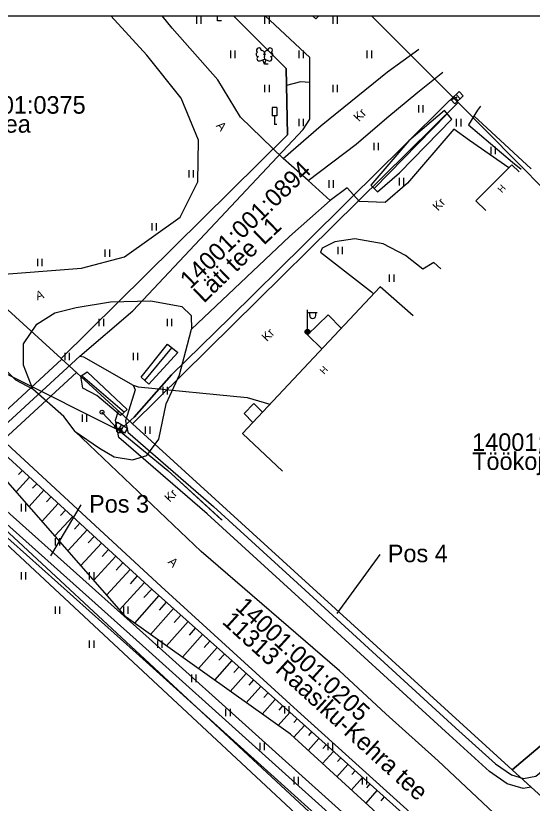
# Model space of a CAD drawing. Extents: x 567864 to 568657, y 6579839 to 6580994.
# Drawn here: x 568425.2 to 568478.2, y 6580410.7 to 6580491.5 of the extents above; entities that cross this region are included whole.
import ezdxf

# ---------------------------------------------------------------- set-up
doc = ezdxf.new("R2010")
doc.units = 0
for name, color, linetype in [('AED', 7, 'Continuous'), ('ELRAJATISMP', 7, 'Continuous'), ('HALJASTUS', 7, 'Continuous'), ('HOONE', 7, 'Continuous'), ('KASUTUSALA', 7, 'Continuous'), ('KPOHULIIN', 7, 'Continuous'), ('LIIKLUS', 7, 'Continuous'), ('MPKAABEL', 7, 'Continuous'), ('MPOHULIIN', 7, 'Continuous'), ('PIIR', 7, 'Continuous'), ('POST', 7, 'Continuous'), ('PR_SIDE', 7, 'Continuous'), ('PUU', 7, 'Continuous'), ('RELJEEF', 7, 'Continuous'), ('TEE', 7, 'Continuous'), ('VORMISTUS_3', 7, 'Continuous')]:
    doc.layers.add(name, color=color, linetype=linetype)

msp = doc.modelspace()

# ---------------------------------------------------------------- linework, layer by layer
at = {"layer": 'AED'}
msp.add_line((568436.38, 6580450.775), (568432.091, 6580454.464), dxfattribs=at)
at = {"layer": 'ELRAJATISMP'}
for p, q in [((568470.216, 6580483.175), (568470.629, 6580482.743)), ((568470.412, 6580483.362), (568470.825, 6580482.931)), ((568436.071, 6580449.542), (568435.765, 6580449.029)), ((568436.304, 6580449.402), (568435.998, 6580448.89))]:
    msp.add_line(p, q, dxfattribs=at)
for points in [[(568469.882, 6580482.855), (568470.746, 6580483.681), (568471.158, 6580483.25), (568470.295, 6580482.424)], [(568435.675, 6580449.778), (568436.7, 6580449.165), (568436.394, 6580448.653), (568435.369, 6580449.266)]]:
    msp.add_lwpolyline(points, close=True, dxfattribs=at)
at = {"layer": 'HALJASTUS'}
for p, q in [((568443.772, 6580491.381), (568443.772, 6580490.619)), ((568444.228, 6580491.381), (568444.228, 6580490.619)), ((568450.772, 6580491.381), (568450.772, 6580490.619)), ((568451.228, 6580491.381), (568451.228, 6580490.619)), ((568457.772, 6580491.381), (568457.772, 6580490.619)), ((568458.228, 6580491.381), (568458.228, 6580490.619)), ((568447.272, 6580487.881), (568447.272, 6580487.119)), ((568447.728, 6580487.881), (568447.728, 6580487.119)), ((568454.272, 6580487.881), (568454.272, 6580487.119)), ((568454.728, 6580487.881), (568454.728, 6580487.119)), ((568461.272, 6580487.881), (568461.272, 6580487.119)), ((568461.728, 6580487.881), (568461.728, 6580487.119)), ((568450.772, 6580484.381), (568450.772, 6580483.619)), ((568451.228, 6580484.381), (568451.228, 6580483.619)), ((568457.772, 6580484.381), (568457.772, 6580483.619)), ((568458.228, 6580484.381), (568458.228, 6580483.619)), ((568466.562, 6580482.291), (568466.562, 6580481.53)), ((568467.017, 6580482.291), (568467.017, 6580481.53)), ((568454.272, 6580480.881), (568454.272, 6580480.119)), ((568454.728, 6580480.881), (568454.728, 6580480.119)), ((568462.026, 6580473.738), (568469.517, 6580481.401)), ((568470.443, 6580480.873), (568470.443, 6580480.112)), ((568470.898, 6580480.873), (568470.898, 6580480.112)), ((568472.25, 6580481.183), (568478.108, 6580475.742)), ((568461.963, 6580478.438), (568461.963, 6580477.677)), ((568462.418, 6580478.438), (568462.418, 6580477.677)), ((568473.978, 6580478.017), (568473.978, 6580477.256)), ((568474.433, 6580478.017), (568474.433, 6580477.256)), ((568442.977, 6580475.614), (568442.977, 6580474.853)), ((568443.432, 6580475.614), (568443.432, 6580474.853)), ((568457.364, 6580474.585), (568457.364, 6580473.823)), ((568457.819, 6580474.585), (568457.819, 6580473.823)), ((568464.577, 6580474.82), (568464.577, 6580474.059)), ((568465.032, 6580474.82), (568465.032, 6580474.059)), ((568439.18, 6580470.19), (568439.18, 6580469.429)), ((568439.635, 6580470.19), (568439.635, 6580469.429)), ((568434.388, 6580467.491), (568434.388, 6580466.73)), ((568434.844, 6580467.491), (568434.844, 6580466.73)), ((568458.269, 6580467.752), (568458.269, 6580466.991)), ((568458.724, 6580467.752), (568458.724, 6580466.991)), ((568427.45, 6580466.521), (568427.45, 6580465.76)), ((568427.905, 6580466.521), (568427.905, 6580465.76)), ((568463.561, 6580464.925), (568463.561, 6580464.164)), ((568464.016, 6580464.925), (568464.016, 6580464.164)), ((568433.772, 6580460.381), (568433.772, 6580459.619)), ((568434.228, 6580460.381), (568434.228, 6580459.619)), ((568440.772, 6580460.381), (568440.772, 6580459.619)), ((568441.228, 6580460.381), (568441.228, 6580459.619)), ((568438.494, 6580454.05), (568441.242, 6580457.406)), ((568430.272, 6580456.881), (568430.272, 6580456.119)), ((568430.728, 6580456.881), (568430.728, 6580456.119)), ((568437.272, 6580456.881), (568437.272, 6580456.119)), ((568437.728, 6580456.881), (568437.728, 6580456.119)), ((568440.324, 6580453.381), (568440.324, 6580452.619)), ((568440.779, 6580453.381), (568440.779, 6580452.619)), ((568432.038, 6580450.564), (568432.038, 6580449.803)), ((568432.493, 6580450.564), (568432.493, 6580449.803)), ((568438.526, 6580449.327), (568438.526, 6580448.566)), ((568438.981, 6580449.327), (568438.981, 6580448.566)), ((568425.772, 6580441.381), (568425.772, 6580440.619)), ((568426.228, 6580441.381), (568426.228, 6580440.619)), ((568429.272, 6580437.881), (568429.272, 6580437.119)), ((568429.728, 6580437.881), (568429.728, 6580437.119)), ((568425.772, 6580434.381), (568425.772, 6580433.619)), ((568426.228, 6580434.381), (568426.228, 6580433.619)), ((568432.772, 6580434.381), (568432.772, 6580433.619)), ((568433.228, 6580434.381), (568433.228, 6580433.619)), ((568429.272, 6580430.881), (568429.272, 6580430.119)), ((568429.728, 6580430.881), (568429.728, 6580430.119)), ((568436.272, 6580430.881), (568436.272, 6580430.119)), ((568436.728, 6580430.881), (568436.728, 6580430.119)), ((568432.772, 6580427.381), (568432.772, 6580426.619)), ((568433.228, 6580427.381), (568433.228, 6580426.619)), ((568439.772, 6580427.381), (568439.772, 6580426.619)), ((568440.228, 6580427.381), (568440.228, 6580426.619)), ((568443.272, 6580423.881), (568443.272, 6580423.119)), ((568443.728, 6580423.881), (568443.728, 6580423.119)), ((568446.772, 6580420.381), (568446.772, 6580419.619)), ((568447.228, 6580420.381), (568447.228, 6580419.619)), ((568452.799, 6580420.654), (568452.799, 6580419.893)), ((568453.254, 6580420.654), (568453.254, 6580419.893)), ((568450.272, 6580416.881), (568450.272, 6580416.119)), ((568450.728, 6580416.881), (568450.728, 6580416.119)), ((568457.272, 6580416.881), (568457.272, 6580416.119)), ((568457.728, 6580416.881), (568457.728, 6580416.119)), ((568453.772, 6580413.381), (568453.772, 6580412.619)), ((568454.228, 6580413.381), (568454.228, 6580412.619)), ((568460.772, 6580413.381), (568460.772, 6580412.619)), ((568461.228, 6580413.381), (568461.228, 6580412.619))]:
    msp.add_line(p, q, dxfattribs=at)
for points in [[(568455.679, 6580491.456), (568456.023, 6580491.13), (568456.344, 6580491.456)], [(568469.23, 6580481.751), (568465.569, 6580478.638), (568461.681, 6580474.088), (568462.36, 6580473.4), (568464.605, 6580475.334), (568469.983, 6580480.833), (568469.23, 6580481.751)], [(568472.919, 6580482.179), (568472.604, 6580481.765), (568471.701, 6580480.282), (568476.216, 6580476.426), (568477.089, 6580475.728)], [(568440.791, 6580457.756), (568441.872, 6580456.916), (568438.89, 6580453.686), (568438.113, 6580454.4), (568440.791, 6580457.756)], [(568436.657, 6580451.066), (568435.99, 6580450.468), (568433.555, 6580452.514), (568432.1, 6580453.247), (568431.917, 6580454.485), (568432.571, 6580454.92), (568436.657, 6580451.066)]]:
    msp.add_lwpolyline(points, dxfattribs=at)
at = {"layer": 'HOONE'}
for points in [[(568476.908, 6580475.43), (568476.153, 6580476.182), (568472.461, 6580472.475), (568473.456, 6580471.485)], [(568466.002, 6580460.689), (568462.617, 6580463.652), (568448.5, 6580448.608), (568452.605, 6580444.756)]]:
    msp.add_lwpolyline(points, dxfattribs=at)
at = {"layer": 'KASUTUSALA'}
msp.add_lwpolyline([(568493.207, 6580374.737), (568460.062, 6580405.872), (568437.58, 6580426.106), (568418.255, 6580443.353), (568417.794, 6580443.764), (568417.1, 6580444.45), (568402.76, 6580458.616), (568388.236, 6580470.827), (568387.31, 6580471.69), (568385.679, 6580473.21), (568386.212, 6580473.528), (568388.359, 6580473.336), (568404.109, 6580460.095), (568418.602, 6580445.777), (568429.97, 6580456.218), (568431.455, 6580454.865), (568420.072, 6580444.412), (568438.915, 6580427.595), (568461.416, 6580407.344), (568494.568, 6580376.202)], dxfattribs=at)
msp.add_lwpolyline([(568477.303, 6580412.2), (568475.657, 6580412.671), (568473.841, 6580413.939), (568469.701, 6580417.689), (568454.272, 6580431.785), (568444.875, 6580440.358), (568435.811, 6580448.207), (568435.47, 6580449.982), (568435.77, 6580450.932), (568437.22, 6580449.61), (568476.19, 6580414.1), (568478.11, 6580412.351)], close=True, dxfattribs=at)
at = {"layer": 'KPOHULIIN'}
msp.add_lwpolyline([(568508.43, 6580360.63), (568460.118, 6580405.359), (568402.883, 6580458.504), (568384.68, 6580466.246)], dxfattribs=at)
at = {"layer": 'LIIKLUS'}
for p, q in [((568451.53, 6580482.056), (568451.53, 6580481.206)), ((568452.03, 6580482.056), (568451.53, 6580482.056)), ((568452.03, 6580482.056), (568452.03, 6580481.206)), ((568452.03, 6580481.206), (568451.53, 6580481.206)), ((568451.78, 6580481.206), (568451.78, 6580480.306)), ((568452.03, 6580480.306), (568451.78, 6580480.306))]:
    msp.add_line(p, q, dxfattribs=at)
at = {"layer": 'MPKAABEL'}
for points in [[(568435.851, 6580448.911), (568437.38, 6580450.298), (568441.22, 6580454.614), (568447.245, 6580460.504), (568454.8, 6580467.949), (568459.571, 6580472.72), (568464.936, 6580477.992), (568469.741, 6580482.773), (568470.51, 6580483.116)], [(568470.51, 6580483.116), (568469.741, 6580482.773), (568464.936, 6580477.992), (568459.571, 6580472.72), (568454.8, 6580467.949), (568447.245, 6580460.504), (568441.22, 6580454.614), (568437.38, 6580450.298), (568435.851, 6580448.911)], [(568435.851, 6580448.911), (568440.843, 6580444.81), (568446.413, 6580439.712)], [(568435.851, 6580448.911), (568440.841, 6580444.812), (568446.315, 6580439.802)]]:
    msp.add_lwpolyline(points, dxfattribs=at)
at = {"layer": 'MPOHULIIN'}
msp.add_lwpolyline([(568435.851, 6580448.911), (568391.527, 6580471.097), (568384.68, 6580475.615)], dxfattribs=at)
at = {"layer": 'PIIR'}
for points in [[(568391.299, 6580491.456), (568392.03, 6580490.79), (568429.88, 6580456.3), (568437.22, 6580449.61), (568476.19, 6580414.1), (568508.43, 6580384.732)], [(568447.578, 6580491.456), (568452.98, 6580486.06), (568453.13, 6580479.23), (568429.88, 6580456.3), (568392.03, 6580490.79), (568392.661, 6580491.456)], [(568461.731, 6580491.456), (568470.64, 6580482.56), (568437.22, 6580449.61), (568429.88, 6580456.3), (568453.13, 6580479.23), (568452.98, 6580486.06), (568447.578, 6580491.456)], [(568508.43, 6580485.337), (568485.66, 6580467.38), (568470.64, 6580482.56), (568461.731, 6580491.456)], [(568508.43, 6580441.348), (568476.19, 6580414.1), (568437.22, 6580449.61), (568470.64, 6580482.56), (568485.66, 6580467.38), (568508.43, 6580485.337)], [(568508.43, 6580358.861), (568387.31, 6580471.69), (568384.68, 6580474.141)], [(568384.68, 6580470.154), (568387.31, 6580471.69), (568508.43, 6580358.861)], [(568508.43, 6580384.732), (568476.19, 6580414.1), (568508.43, 6580441.348)]]:
    msp.add_lwpolyline(points, dxfattribs=at)
at = {"layer": 'POST'}
for p, q in [((568455.176, 6580459.279), (568455.176, 6580461.279)), ((568455.176, 6580461.029), (568456.176, 6580461.029)), ((568455.402, 6580460.708), (568455.402, 6580461.029)), ((568456.015, 6580460.708), (568456.015, 6580461.029)), ((568455.176, 6580459.029), (568455.176, 6580459.029))]:
    msp.add_line(p, q, dxfattribs=at)
msp.add_lwpolyline([(568434.08, 6580450.796), (568435.851, 6580448.911)], dxfattribs=at)
for centre, radius in [((568455.176, 6580459.029), 0.25), ((568455.176, 6580459.029), 0.225), ((568455.176, 6580459.029), 0.2), ((568455.176, 6580459.029), 0.175), ((568455.176, 6580459.029), 0.15), ((568455.176, 6580459.029), 0.125), ((568455.176, 6580459.029), 0.1), ((568455.176, 6580459.029), 0.075), ((568455.176, 6580459.029), 0.05), ((568455.176, 6580459.029), 0.025), ((568434.08, 6580450.796), 0.2), ((568435.851, 6580448.911), 0.25)]:
    msp.add_circle(centre, radius, dxfattribs=at)
msp.add_arc((568455.709, 6580460.708), 0.306, 180, 0, dxfattribs=at)
at = {"layer": 'PR_SIDE'}
for points in [[(568455.401, 6580484.611), (568455.401, 6580487.168), (568450.837, 6580491.456)], [(568365.055, 6580475.025), (568365.72, 6580474.689), (568366.357, 6580474.88), (568372.77, 6580480.661), (568373.5, 6580480.629), (568382.621, 6580470.383), (568382.924, 6580470.401), (568386.446, 6580472.503), (568387.957, 6580472.369), (568403.435, 6580459.356), (568418.48, 6580444.494), (568418.81, 6580444.61), (568431.813, 6580456.552), (568437.233, 6580461.195), (568454.71, 6580479.772), (568455.401, 6580480.844), (568455.401, 6580484.611)], [(568455.401, 6580484.611), (568454.444, 6580484.677), (568453.019, 6580484.299)], [(568431.813, 6580456.552), (568432.198, 6580456.461), (568437.292, 6580453.582)], [(568437.292, 6580453.582), (568437.498, 6580453.084), (568436.5, 6580449.922), (568436.728, 6580448.737), (568445.54, 6580441.106), (568454.946, 6580432.524), (568470.375, 6580418.429), (568474.466, 6580414.723), (568476.093, 6580413.587), (568477.351, 6580413.227), (568478.62, 6580413.465), (568488.626, 6580421.658), (568489.887, 6580422.056), (568492.08, 6580421.21), (568508.662, 6580420.568), (568511.852, 6580420.197), (568512.12, 6580420.126), (568512.341, 6580419.855)], [(568437.292, 6580453.582), (568437.782, 6580453.404), (568448.982, 6580452.292), (568451.31, 6580451.603)], [(568418.48, 6580444.494), (568438.248, 6580426.851), (568460.739, 6580406.609), (568493.888, 6580375.47), (568520.606, 6580350.928), (568532.176, 6580339.842), (568577.376, 6580298.14), (568583.801, 6580292.735), (568596.758, 6580277.054), (568604.332, 6580268.007), (568619.547, 6580250.982), (568628.574, 6580238.417), (568627.426, 6580222.172)]]:
    msp.add_lwpolyline(points, dxfattribs=at)
at = {"layer": 'PUU'}
for p, q in [((568445.95, 6580490.942), (568445.95, 6580491.442)), ((568446.35, 6580490.942), (568445.95, 6580490.942)), ((568450.307, 6580486.829), (568450.752, 6580487.004)), ((568450.747, 6580486.494), (568450.572, 6580486.934)), ((568450.747, 6580486.494), (568450.927, 6580486.934)), ((568451.127, 6580486.494), (568450.747, 6580486.494)), ((568450.752, 6580487.004), (568451.192, 6580486.824))]:
    msp.add_line(p, q, dxfattribs=at)
msp.add_lwpolyline([(568450.752, 6580487.499), (568450.732, 6580487.424), (568450.732, 6580487.404), (568450.742, 6580487.374), (568450.762, 6580487.339), (568450.767, 6580487.319), (568450.752, 6580487.284), (568450.727, 6580487.234), (568450.722, 6580487.209), (568450.727, 6580487.194), (568450.737, 6580487.164), (568450.772, 6580487.104), (568450.777, 6580487.084), (568450.772, 6580487.064), (568450.757, 6580487.029), (568450.752, 6580487.004)], dxfattribs=at)
for centre, radius, start, end in [((568445.95, 6580491.942), 0.5, 256.7038, 283.2962), ((568450.19, 6580487.908), 0.256, 111.50269, 232.51731), ((568450.19, 6580487.908), 0.256, 350.48556, 111.50017), ((568451.326, 6580487.899), 0.256, 67.6168, 188.63142), ((568451.326, 6580487.899), 0.256, 306.59966, 67.61428), ((568450.116, 6580487.496), 0.224, 111.43041, 274.49868), ((568450.221, 6580487.052), 0.237, 111.50143, 291.50036), ((568450.525, 6580487.657), 0.224, 308.50412, 111.57247), ((568450.751, 6580487.261), 0.237, 66.76552, 111.50149), ((568450.988, 6580487.653), 0.225, 67.7016, 230.51262), ((568451.282, 6580487.044), 0.237, 247.61661, 67.61554), ((568451.394, 6580487.486), 0.224, 264.6183, 67.68657)]:
    msp.add_arc(centre, radius, start, end, dxfattribs=at)
at = {"layer": 'RELJEEF'}
for p, q in [((568425.915, 6580444.811), (568425.526, 6580444.387)), ((568426.652, 6580444.135), (568425.28, 6580442.639)), ((568428.126, 6580442.784), (568426.605, 6580441.126)), ((568427.389, 6580443.459), (568426.955, 6580442.986)), ((568428.863, 6580442.108), (568428.385, 6580441.586)), ((568429.6, 6580441.432), (568427.931, 6580439.612)), ((568430.337, 6580440.756), (568429.814, 6580440.185)), ((568431.074, 6580440.08), (568429.256, 6580438.098)), ((568432.548, 6580438.728), (568430.582, 6580436.584)), ((568431.811, 6580439.404), (568431.243, 6580438.785)), ((568433.285, 6580438.052), (568432.673, 6580437.384)), ((568434.022, 6580437.376), (568431.907, 6580435.07)), ((568434.759, 6580436.7), (568434.102, 6580435.984)), ((568435.496, 6580436.024), (568433.232, 6580433.556)), ((568436.97, 6580434.672), (568434.558, 6580432.043)), ((568436.233, 6580435.348), (568435.531, 6580434.584)), ((568437.706, 6580433.996), (568436.961, 6580433.183)), ((568438.443, 6580433.32), (568435.883, 6580430.529)), ((568439.18, 6580432.644), (568438.39, 6580431.783)), ((568439.926, 6580431.978), (568437.41, 6580429.155)), ((568441.419, 6580430.647), (568439.05, 6580427.99)), ((568440.672, 6580431.312), (568439.94, 6580430.49)), ((568442.165, 6580429.981), (568441.477, 6580429.209)), ((568442.912, 6580429.316), (568440.69, 6580426.824)), ((568443.658, 6580428.651), (568443.014, 6580427.928)), ((568444.405, 6580427.985), (568442.33, 6580425.658)), ((568445.897, 6580426.654), (568443.97, 6580424.492)), ((568445.151, 6580427.32), (568444.551, 6580426.646)), ((568446.644, 6580425.989), (568446.088, 6580425.365)), ((568447.39, 6580425.323), (568445.61, 6580423.326)), ((568448.137, 6580424.658), (568447.625, 6580424.083)), ((568448.883, 6580423.993), (568447.25, 6580422.16)), ((568450.376, 6580422.662), (568448.89, 6580420.994)), ((568449.63, 6580423.327), (568449.162, 6580422.802)), ((568451.123, 6580421.996), (568450.699, 6580421.521)), ((568451.869, 6580421.331), (568450.53, 6580419.828)), ((568452.616, 6580420.665), (568452.236, 6580420.239)), ((568453.362, 6580420), (568452.17, 6580418.662)), ((568454.108, 6580419.334), (568453.772, 6580418.958)), ((568454.853, 6580418.667), (568453.767, 6580417.454)), ((568455.598, 6580418), (568455.27, 6580417.634)), ((568456.343, 6580417.333), (568455.244, 6580416.106)), ((568457.088, 6580416.665), (568456.756, 6580416.295)), ((568457.833, 6580415.998), (568456.721, 6580414.757)), ((568458.578, 6580415.331), (568458.242, 6580414.957)), ((568459.322, 6580414.664), (568458.198, 6580413.408)), ((568460.067, 6580413.997), (568459.728, 6580413.618)), ((568460.812, 6580413.33), (568459.675, 6580412.06)), ((568461.557, 6580412.662), (568461.214, 6580412.279)), ((568462.302, 6580411.995), (568461.152, 6580410.711)), ((568463.047, 6580411.328), (568462.7, 6580410.941))]:
    msp.add_line(p, q, dxfattribs=at)
for points in [[(568508.43, 6580369.908), (568508.363, 6580369.97), (568491.192, 6580385.824), (568473.185, 6580402.248), (568453.996, 6580419.435), (568439.254, 6580432.576), (568424.484, 6580446.124), (568410.28, 6580459.769), (568392.732, 6580475.544), (568387.587, 6580476.456), (568384.68, 6580475.798)], [(568508.43, 6580367.153), (568506.784, 6580368.671), (568490.34, 6580384.468), (568471.539, 6580401.225), (568453.41, 6580417.781), (568436.551, 6580429.766), (568424.43, 6580443.611), (568407.632, 6580458.36), (568391.91, 6580472.015), (568385.007, 6580473.1), (568384.68, 6580472.903)]]:
    msp.add_lwpolyline(points, dxfattribs=at)
at = {"layer": 'TEE'}
for points in [[(568508.43, 6580378.848), (568495.331, 6580390.846), (568482.748, 6580402.025), (568475.413, 6580408.617), (568468.573, 6580415.051), (568463.218, 6580419.847), (568458.453, 6580424.255), (568444.275, 6580436.505), (568431.318, 6580448.81), (568430.178, 6580450.348), (568426.969, 6580453.169), (568425.251, 6580454.077), (568411.891, 6580467.485), (568409.943, 6580469.266), (568402.862, 6580475.838), (568393.707, 6580484.18), (568385.876, 6580491.456)], [(568411.891, 6580467.485), (568415.882, 6580465.074), (568420.903, 6580464.715), (568425.819, 6580465.089), (568431.98, 6580465.58), (568436.401, 6580466.715), (568442.096, 6580470.806), (568443.907, 6580474.414), (568443.977, 6580478.683), (568442.212, 6580482.999), (568438.678, 6580487.427), (568434.981, 6580491.456)], [(568426.969, 6580453.169), (568426.04, 6580455.624), (568426.04, 6580457.796), (568427.401, 6580459.807), (568429.249, 6580460.974), (568431.436, 6580461.533), (568434.953, 6580462.101), (568439.093, 6580462.214), (568442.269, 6580461.647), (568443.217, 6580460.715), (568443.282, 6580459.32), (568453.309, 6580468.816), (568457.506, 6580472.505), (568455.25, 6580474.572), (568452.658, 6580476.809), (568448.298, 6580481.07), (568445.963, 6580484.873), (568441.272, 6580490.194), (568440.254, 6580491.456)], [(568452.658, 6580476.809), (568456.583, 6580480.188), (568463.384, 6580485.693), (568466.608, 6580488.043)], [(568455.25, 6580474.572), (568460.16, 6580478.279), (568463.297, 6580480.985), (568466.509, 6580483.605), (568469.046, 6580485.675)], [(568475.819, 6580475.846), (568471.809, 6580478.673), (568470.185, 6580479.817), (568465.421, 6580474.296), (568463.153, 6580472.286), (568460.495, 6580472.416), (568459.231, 6580473.81), (568457.506, 6580472.505)], [(568384.68, 6580477.004), (568386.096, 6580477.365), (568389.562, 6580477.715), (568393.349, 6580475.969), (568411.045, 6580459.971), (568424.789, 6580447.111), (568440.147, 6580432.905), (568454.13, 6580420.179), (568473.798, 6580402.405), (568491.299, 6580386.419), (568508.43, 6580370.472)], [(568468.865, 6580465.493), (568468.152, 6580466.141), (568467.018, 6580465.46), (568465.235, 6580466.855), (568462.934, 6580468.054), (568460.017, 6580468.573), (568457.976, 6580468.281), (568456.679, 6580467.633), (568456.517, 6580467.211), (568461.735, 6580463.126), (568461.951, 6580462.943)], [(568458.642, 6580459.416), (568457.306, 6580460.793), (568455.186, 6580458.743), (568456.654, 6580457.298)], [(568431.318, 6580448.81), (568433.81, 6580447.104), (568435.333, 6580446.229), (568437.213, 6580445.904), (568438.671, 6580446.358), (568439.903, 6580448.012), (568440.656, 6580451.636), (568442.018, 6580454.619), (568442.86, 6580457.731), (568443.282, 6580459.32)], [(568450.567, 6580450.811), (568449.65, 6580451.684), (568448.687, 6580450.645), (568449.571, 6580449.75)]]:
    msp.add_lwpolyline(points, dxfattribs=at)
at = {"layer": 'VORMISTUS_3'}
for p, q in [((568428.826, 6580436.055), (568431.959, 6580441.301)), ((568458.216, 6580430.16), (568462.612, 6580436.215))]:
    msp.add_line(p, q, dxfattribs=at)
msp.add_lwpolyline([(568508.43, 6580333.956), (568384.68, 6580333.956), (568384.68, 6580491.456), (568508.43, 6580491.456)], close=True, dxfattribs=at)

# ---------------------------------------------------------------- texts
at = {"layer": 'HOONE'}
for p in [(568475.124, 6580473.24), (568456.874, 6580454.624)]:
    msp.add_text('H', height=0.7, rotation=47.67049, dxfattribs=at).set_placement(p)
at = {"layer": 'PIIR'}
for s, p in [('14001:001:0375', (568415.001, 6580481.411)), ('Meelespea', (568415.001, 6580479.461)), ('14001:001:0288', (568472.069, 6580446.824)), ('Töökoja', (568472.069, 6580444.874))]:
    msp.add_text(s, height=1.8, dxfattribs=at).set_placement(p)
for s, rotation, p in [('14001:001:0894', 43.92272, (568443.145, 6580463.354)), ('Läti tee L1', 43.92272, (568444.533, 6580461.914)), ('14001:001:0205', 317.70635, (568447.665, 6580430.669)), ('11313 Raasiku-Kehra tee', 317.70635, (568446.319, 6580429.19))]:
    msp.add_text(s, height=1.8, rotation=rotation, dxfattribs=at).set_placement(p)
at = {"layer": 'TEE'}
for s, rotation, p in [('Kr', 46.59978, (568460.45, 6580480.542)), ('A', 310.26404, (568445.745, 6580480.146)), ('Kr', 46.59978, (568468.568, 6580471.377)), ('A', 19.34151, (568427.447, 6580462.255)), ('Kr', 46.59978, (568451.019, 6580457.991)), ('Kr', 46.59978, (568441.048, 6580441.503)), ('A', 315.25757, (568440.786, 6580435.373))]:
    msp.add_text(s, height=0.9, rotation=rotation, dxfattribs=at).set_placement(p)
at = {"layer": 'VORMISTUS_3'}
for s, p in [('Pos 3', (568432.758, 6580440.493)), ('Pos 4', (568463.411, 6580435.408))]:
    msp.add_text(s, height=1.8, dxfattribs=at).set_placement(p)

doc.saveas('drawing.dxf')
